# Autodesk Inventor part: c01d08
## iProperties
Created: 2004-05
Part Number: c01d08
Document SubType Name: Modeling
Designer: CADCIM Technologies
Manufacturer: Standard
Standards Organization: Custom
Author: CADCIM Technologies
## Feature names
1. Extrusion1
